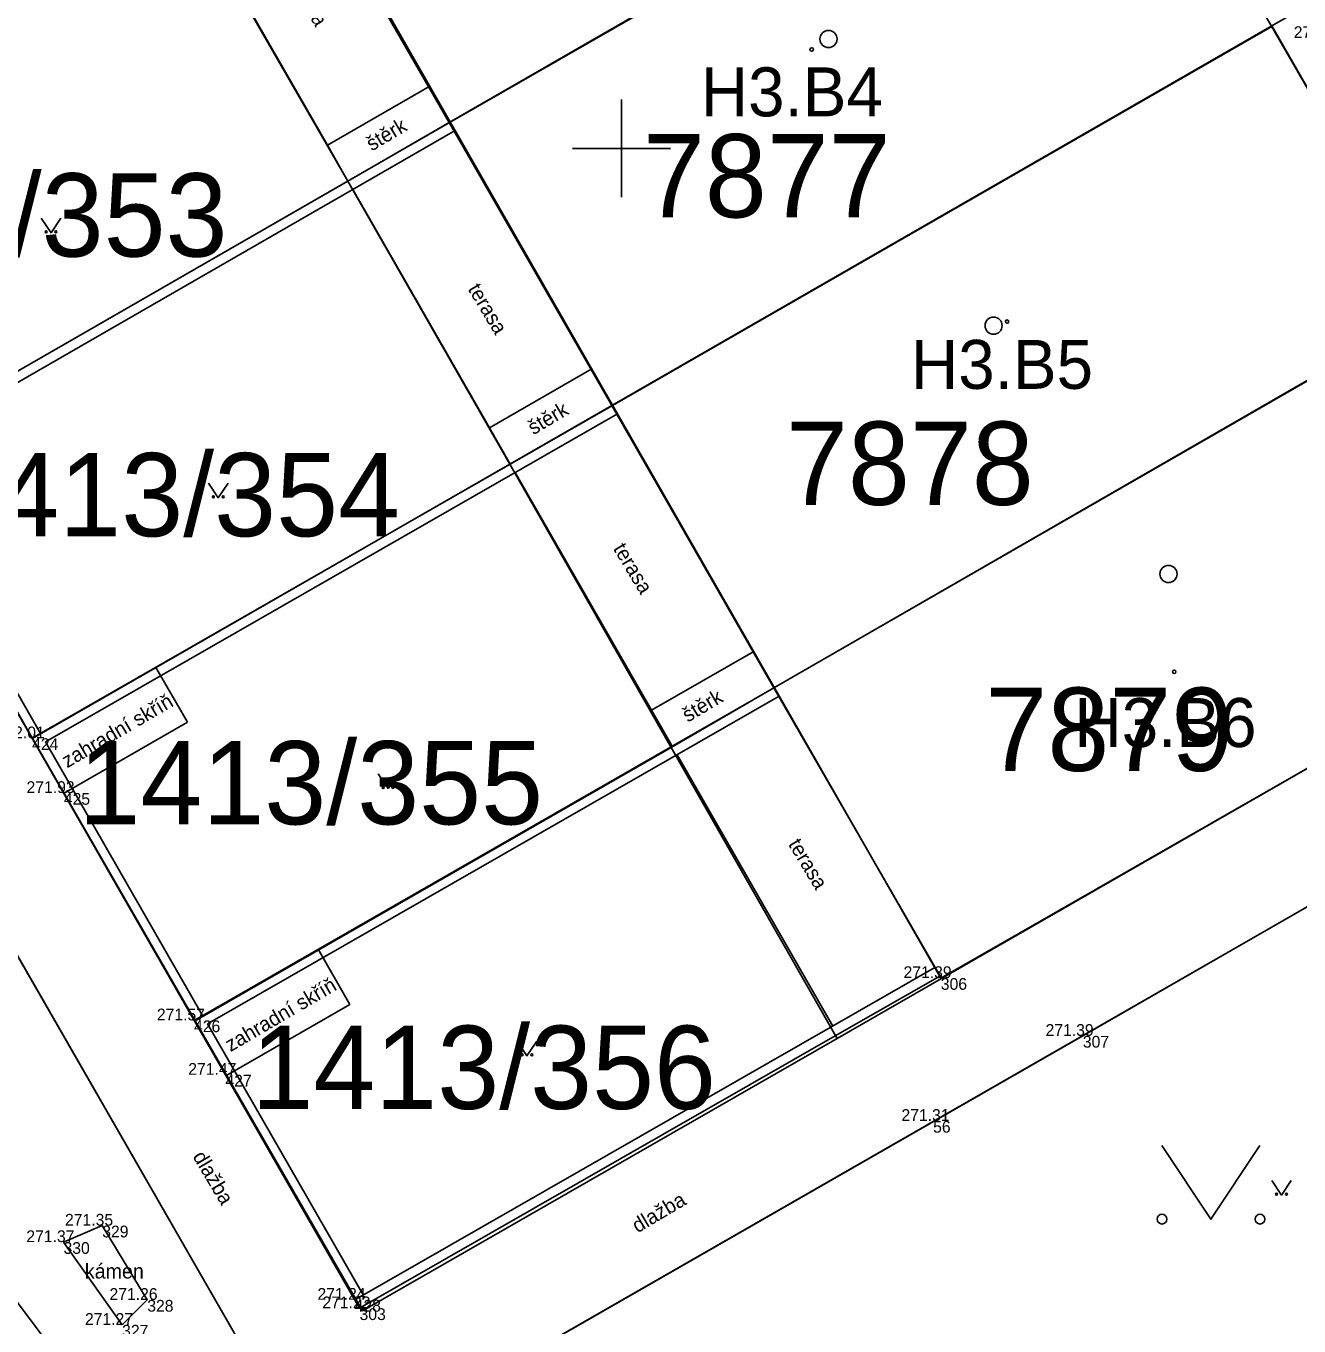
# Model space of a CAD drawing. Extents: x -771260 to -770828, y -1053564 to -1052811.
# Drawn here: x -770962.16 to -770936.17, y -1053224.04 to -1053197.5 of the extents above; entities that cross this region are included whole.
import ezdxf

# ---------------------------------------------------------------- set-up
doc = ezdxf.new("R2010")
doc.units = 0
for name, color, linetype in [('14_8_2023_krizky', 7, 'Continuous'), ('25_10_2019_budova', 7, 'Continuous'), ('25_10_2019_dlazba', 7, 'Continuous'), ('25_10_2019_kameny', 7, 'Continuous'), ('25_10_2019_operna_stena', 7, 'Continuous'), ('25_10_2019_popis_objektu', 7, 'Continuous'), ('25_10_2019_popis_povrchu', 7, 'Continuous'), ('25_10_2019_sterk', 7, 'Continuous'), ('25_10_2019_terasa', 7, 'Continuous'), ('25_10_2019_zahradni_skrin', 7, 'Continuous'), ('25_10_2019_zamereny_bod', 7, 'Continuous'), ('25_10_2019_zamereny_bod_cislo', 7, 'Continuous'), ('25_10_2019_zamereny_bod_vyska', 7, 'Continuous'), ('25_10_2019_znacka_budovy', 7, 'Continuous'), ('25_10_2019_znacka_zelen', 7, 'Continuous'), ('25_3_2019_krizky_JTSK', 7, 'Continuous'), ('Default', 7, 'Continuous'), ('DKM_Hranice parcel', 7, 'Continuous'), ('DKM_Parcelní čísla', 7, 'Continuous'), ('DKM_Vnitřní kresba', 7, 'Continuous'), ('DKM_Značky budov', 7, 'Continuous'), ('DKM_Značky kultur', 7, 'Continuous')]:
    doc.layers.add(name, color=color, linetype=linetype)

# ---------------------------------------------------------------- blocks, each defined once
blk = doc.blocks.new('4.020')
at = {"layer": '25_10_2019_znacka_budovy'}
blk.add_circle((0, 0), 1.75, dxfattribs=at)
blk = doc.blocks.new('3.140')
at = {"layer": '25_10_2019_znacka_zelen'}
blk.add_lwpolyline([(-10, 15), (0, 0), (10, 15)], dxfattribs=at)
for centre in [(-5, 1), (-5, 1), (5, 1), (5, 1)]:
    blk.add_circle(centre, 1, dxfattribs=at)
blk = doc.blocks.new('POINT_DISPLAY')
at = {"layer": 'Default'}
blk.add_line((0, 0), (0, 0), dxfattribs=at)
blk = doc.blocks.new('KRIZEK')
at = {"layer": '25_3_2019_krizky_JTSK'}
for p, q in [((0, 10), (0, -10)), ((-10, 0), (10, 0))]:
    blk.add_line(p, q, dxfattribs=at)

msp = doc.modelspace()

# ---------------------------------------------------------------- linework, layer by layer
at = {"layer": '25_10_2019_budova'}
for p, q in [((-770950.052, -1053174.33), (-770930.001, -1053209.22)), ((-770943.484, -1053216.938), (-770963.511, -1053181.988)), ((-770953.496, -1053199.466), (-770940.048, -1053191.737)), ((-770950.183, -1053205.248), (-770936.728, -1053197.515)), ((-770946.881, -1053211.009), (-770933.431, -1053203.252)), ((-770930.001, -1053209.22), (-770943.484, -1053216.938))]:
    msp.add_line(p, q, dxfattribs=at)
at = {"layer": '25_10_2019_dlazba'}
for p, q in [((-770977.395, -1053190.28), (-770957.487, -1053224.903)), ((-770940.585, -1053218.118), (-770928.78, -1053211.313)), ((-770958.68, -1053228.498), (-770940.585, -1053218.118))]:
    msp.add_line(p, q, dxfattribs=at)
at = {"layer": '25_10_2019_kameny'}
for p, q in [((-770960.599, -1053221.992), (-770961.39, -1053222.328)), ((-770959.681, -1053223.507), (-770960.599, -1053221.992)), ((-770961.39, -1053222.328), (-770960.194, -1053224.017)), ((-770960.194, -1053224.017), (-770959.681, -1053223.507))]:
    msp.add_line(p, q, dxfattribs=at)
at = {"layer": '25_10_2019_operna_stena'}
for p, q in [((-770975.283, -1053188.99), (-770955.348, -1053223.679)), ((-770965.339, -1053206.284), (-770953.496, -1053199.466)), ((-770965.069, -1053206.36), (-770953.397, -1053199.639)), ((-770962.03, -1053212.042), (-770950.183, -1053205.248)), ((-770961.761, -1053212.118), (-770950.083, -1053205.421)), ((-770965.069, -1053206.36), (-770961.86, -1053211.945)), ((-770958.725, -1053217.801), (-770946.881, -1053211.009)), ((-770958.452, -1053217.875), (-770946.782, -1053211.183)), ((-770961.761, -1053212.118), (-770958.552, -1053217.702)), ((-770945.692, -1053217.92), (-770943.606, -1053216.725)), ((-770945.592, -1053218.093), (-770943.507, -1053216.898)), ((-770958.452, -1053217.875), (-770955.274, -1053223.407)), ((-770955.447, -1053223.506), (-770945.692, -1053217.92)), ((-770955.348, -1053223.679), (-770945.592, -1053218.093))]:
    msp.add_line(p, q, dxfattribs=at)
at = {"layer": '25_10_2019_sterk'}
for p, q in [((-770955.584, -1053200.668), (-770956.005, -1053199.934)), ((-770952.271, -1053206.445), (-770952.697, -1053205.703)), ((-770948.968, -1053212.206), (-770949.389, -1053211.472))]:
    msp.add_line(p, q, dxfattribs=at)
at = {"layer": '25_10_2019_terasa'}
for p, q in [((-770956.005, -1053199.934), (-770958.789, -1053195.079)), ((-770956.005, -1053199.934), (-770953.916, -1053198.733)), ((-770952.697, -1053205.703), (-770955.485, -1053200.841)), ((-770952.697, -1053205.703), (-770950.61, -1053204.503)), ((-770949.389, -1053211.472), (-770952.172, -1053206.619)), ((-770949.389, -1053211.472), (-770947.303, -1053210.272)), ((-770945.691, -1053217.92), (-770948.868, -1053212.379))]:
    msp.add_line(p, q, dxfattribs=at)
at = {"layer": '25_10_2019_zahradni_skrin'}
for p, q in [((-770958.863, -1053211.714), (-770959.507, -1053210.595)), ((-770961.389, -1053213.168), (-770958.863, -1053211.714)), ((-770955.546, -1053217.478), (-770956.196, -1053216.351)), ((-770958.075, -1053218.933), (-770955.546, -1053217.478))]:
    msp.add_line(p, q, dxfattribs=at)
at = {"layer": 'DKM_Hranice parcel'}
for p, q in [((-770958.9, -1053194.91), (-770955.59, -1053200.67)), ((-770965.33, -1053206.28), (-770955.59, -1053200.67)), ((-770955.59, -1053200.67), (-770952.28, -1053206.45)), ((-770962.02, -1053212.05), (-770965.33, -1053206.28)), ((-770962.02, -1053212.05), (-770952.28, -1053206.45)), ((-770952.28, -1053206.45), (-770948.99, -1053212.23)), ((-770958.7, -1053217.81), (-770962.02, -1053212.05)), ((-770958.7, -1053217.81), (-770948.99, -1053212.23)), ((-770948.99, -1053212.23), (-770945.6, -1053218.17))]:
    msp.add_line(p, q, dxfattribs=at)
for points in [[(-770955.59, -1053200.67), (-770953.52, -1053199.47), (-770940.05, -1053191.71), (-770934.66, -1053188.61)], [(-770984.27, -1053194.26), (-770977.39, -1053190.28), (-770957.49, -1053224.9), (-770960.18, -1053226.44)], [(-770960.18, -1053226.44), (-770967.88, -1053216.14), (-770984.27, -1053194.26)], [(-770952.28, -1053206.45), (-770950.2, -1053205.25), (-770936.73, -1053197.5), (-770931.33, -1053194.39)], [(-770948.99, -1053212.23), (-770946.89, -1053211.01), (-770933.42, -1053203.26), (-770928.02, -1053200.16)], [(-770928.02, -1053200.16), (-770924.59, -1053206.11), (-770930, -1053209.21), (-770943.47, -1053216.95), (-770945.6, -1053218.17)], [(-770958.65, -1053228.48), (-770923.44, -1053208.27), (-770918.35, -1053217.14)], [(-770945.6, -1053218.17), (-770955.29, -1053223.73), (-770958.7, -1053217.81)]]:
    msp.add_lwpolyline(points, dxfattribs=at)
at = {"layer": 'DKM_Vnitřní kresba'}
for p, q in [((-770956.83, -1053193.71), (-770953.52, -1053199.47)), ((-770933.42, -1053203.26), (-770936.73, -1053197.5)), ((-770953.52, -1053199.47), (-770950.2, -1053205.25)), ((-770950.2, -1053205.25), (-770946.89, -1053211.01)), ((-770946.89, -1053211.01), (-770943.47, -1053216.95))]:
    msp.add_line(p, q, dxfattribs=at)
at = {"layer": 'DKM_Značky budov'}
for centre in [(-770945.777, -1053197.769), (-770942.407, -1053203.619), (-770938.837, -1053208.689)]:
    msp.add_circle(centre, 0.175, dxfattribs=at)
at = {"layer": 'DKM_Značky kultur'}
msp.add_lwpolyline([(-770938.97, -1053220.359), (-770937.97, -1053221.86), (-770936.97, -1053220.359)], dxfattribs=at)
for centre in [(-770938.97, -1053221.859), (-770936.97, -1053221.859)]:
    msp.add_circle(centre, 0.1, dxfattribs=at)

# ---------------------------------------------------------------- block references
at = {"layer": '14_8_2023_krizky', "xscale": 0.1, "yscale": 0.10000000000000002}
msp.add_blockref('KRIZEK', (-770950, -1053200), dxfattribs=at)
at = {"layer": '25_10_2019_zamereny_bod', "xscale": 0.1, "yscale": 0.10000000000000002}
for p in [(-770962.031, -1053212.043), (-770961.384, -1053213.16), (-770943.484, -1053216.938), (-770958.726, -1053217.802), (-770940.585, -1053218.118), (-770958.086, -1053218.913), (-770943.641, -1053219.854), (-770960.6, -1053221.992), (-770961.39, -1053222.328), (-770959.681, -1053223.508), (-770955.447, -1053223.506), (-770955.348, -1053223.679), (-770960.194, -1053224.017)]:
    msp.add_blockref('POINT_DISPLAY', p, dxfattribs=at)
at = {"layer": '25_10_2019_znacka_budovy', "xscale": 0.020000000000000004, "yscale": 0.020000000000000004}
for p in [(-770946.12, -1053197.982), (-770942.132, -1053203.536), (-770938.719, -1053210.686)]:
    msp.add_blockref('4.020', p, dxfattribs=at)
at = {"layer": '25_10_2019_znacka_zelen', "xscale": 0.020000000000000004, "yscale": 0.020000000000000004}
for p in [(-770961.645, -1053201.724), (-770958.232, -1053207.133), (-770954.766, -1053213.066), (-770951.931, -1053218.527), (-770936.53, -1053221.367)]:
    msp.add_blockref('3.140', p, dxfattribs=at)

# ---------------------------------------------------------------- texts
at = {"layer": '25_10_2019_popis_objektu'}
for s, rotation, p in [('terasa', 301.0481, (-770956.817, -1053196.583)), ('terasa', 301.0481, (-770953.148, -1053202.871)), ('terasa', 301.0481, (-770950.181, -1053208.17)), ('zahradní skříň', 30.3604, (-770961.316, -1053212.658)), ('terasa', 301.0481, (-770946.608, -1053214.203)), ('zahradní skříň', 30.3604, (-770957.983, -1053218.452))]:
    msp.add_text(s, height=0.3, rotation=rotation, dxfattribs=at).set_placement(p)
for s, height, p in [('H3.B4', 1, (-770948.383, -1053199.347)), ('H3.B5', 1, (-770944.094, -1053204.91)), ('H3.B6', 1, (-770940.757, -1053212.222)), ('kámen', 0.3, (-770960.955, -1053223.071))]:
    msp.add_text(s, height=height, dxfattribs=at).set_placement(p)
at = {"layer": '25_10_2019_popis_povrchu'}
for s, rotation, p in [('štěrk', 30.687, (-770955.099, -1053200.065)), ('štěrk', 30.687, (-770951.801, -1053205.859)), ('štěrk', 30.687, (-770948.649, -1053211.726)), ('dlažba', 300.687, (-770958.764, -1053220.579)), ('dlažba', 30.687, (-770949.673, -1053222.151))]:
    msp.add_text(s, height=0.3, rotation=rotation, dxfattribs=at).set_placement(p)
at = {"layer": '25_10_2019_zamereny_bod_cislo'}
for s, p in [('424', (-770962.031, -1053212.283)), ('425', (-770961.384, -1053213.4)), ('306', (-770943.484, -1053217.178)), ('426', (-770958.726, -1053218.042)), ('307', (-770940.585, -1053218.358)), ('427', (-770958.086, -1053219.153)), ('56', (-770943.641, -1053220.094)), ('329', (-770960.6, -1053222.232)), ('330', (-770961.39, -1053222.568)), ('328', (-770959.681, -1053223.748)), ('428', (-770955.447, -1053223.746)), ('303', (-770955.348, -1053223.919)), ('327', (-770960.194, -1053224.257))]:
    msp.add_text(s, height=0.24, dxfattribs=at).set_placement(p)
at = {"layer": '25_10_2019_zamereny_bod_vyska'}
for s, p in [('272.62 ', (-770936.28, -1053197.749)), ('272.01 ', (-770962.756, -1053212.043)), ('271.93 ', (-770962.145, -1053213.16)), ('271.39 ', (-770944.245, -1053216.938)), ('271.57 ', (-770959.485, -1053217.802)), ('271.39 ', (-770941.346, -1053218.118)), ('271.47 ', (-770958.845, -1053218.913)), ('271.31 ', (-770944.287, -1053219.854)), ('271.35 ', (-770961.36, -1053221.992)), ('271.37 ', (-770962.149, -1053222.328)), ('271.26 ', (-770960.452, -1053223.508)), ('271.24 ', (-770956.207, -1053223.506)), ('271.22 ', (-770956.108, -1053223.679)), ('271.27 ', (-770960.953, -1053224.017))]:
    msp.add_text(s, height=0.24, dxfattribs=at).set_placement(p)
at = {"layer": 'DKM_Parcelní čísla'}
for s, p in [('7877', (-770949.564, -1053201.41)), ('1413/353', (-770967.525, -1053202.21)), ('7878', (-770946.644, -1053207.279)), ('1413/354', (-770964.005, -1053207.92)), ('7879', (-770942.574, -1053212.71)), ('1413/355', (-770961.085, -1053213.8)), ('1413/356', (-770957.555, -1053219.61))]:
    msp.add_text(s, height=1.7, dxfattribs=at).set_placement(p)

doc.saveas('drawing.dxf')
